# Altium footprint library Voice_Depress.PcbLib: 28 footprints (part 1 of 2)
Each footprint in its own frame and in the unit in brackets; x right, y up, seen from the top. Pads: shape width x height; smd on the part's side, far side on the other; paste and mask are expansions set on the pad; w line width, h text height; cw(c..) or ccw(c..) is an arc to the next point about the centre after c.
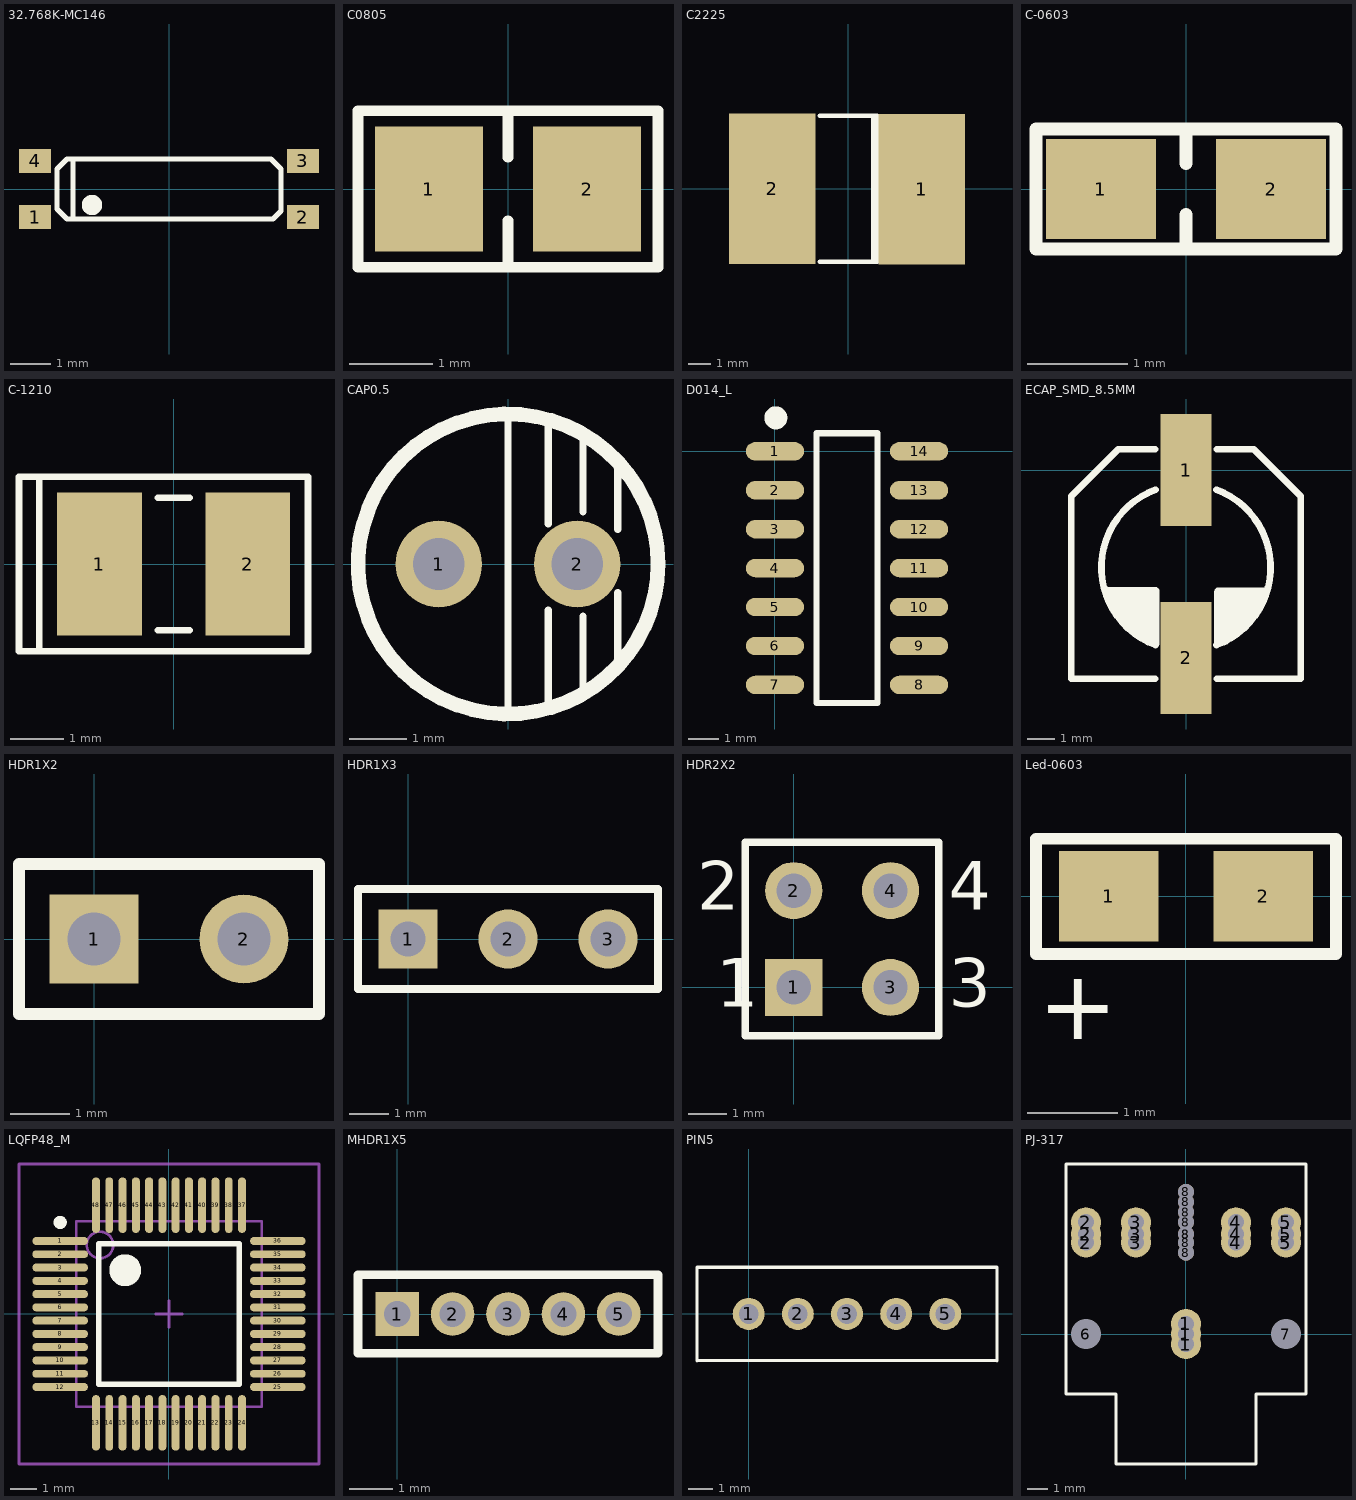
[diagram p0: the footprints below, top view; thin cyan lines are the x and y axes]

## 32.768K-MC146 [mm] "XTAL-32.768K"
pads (4):
  rect 0.8x0.6 smd: 1(-3.35,-0.7) 2(3.35,-0.7) 3(3.35,0.7) 4(-3.35,0.7)
Top Overlay:
  circle w0.254: c-1.927,-0.4 r0.127
  lines w0.127: -2.4,-0.75 -2.4,0.75 ; -2.8,-0.5 -2.55,-0.75 2.6,-0.75 2.8,-0.55 2.8,0.5 2.55,0.75 -2.55,0.75 -2.8,0.5 -2.8,-0.5

## C0805 [mm]
pads (2):
  rect 1.3x1.5 smd: 1(-0.95,0) 2(0.95,0)
Top Overlay:
  lines w0.127: 0,-0.94 0,-0.381 ; 0,0.381 0,0.889 ; -1.803,-0.94 -1.803,0.94 1.803,0.94 1.803,-0.94 -1.803,-0.94
3D body: height 1.2, standoff 0, extent -1.016,-0.584 0.984,0.616

## C2225 [mm] "Chip Capacitor; Body 5.6 x 6.4 mm (LxW typ)"
height 1.1
pads (2):
  rect 3.9x6.8 smd: 1(3.302,-0.025) 2(-3.429,0)
Top Overlay:
  lines w0.2: -1.3,-3.3 1.3,-3.3 1.3,3.3 -1.3,3.3 ; 1.11,-3.3 1.11,3.3
3D body: height 4.5, standoff -0.01, extent -2.857,-2.6 2.857,2.6

## C-0603 [mm]
height 0.5
pads (2):
  rect 1.1x1 smd: 1(-0.85,0) 2(0.85,0)
Top Overlay:
  lines w0.127: 0,-0.6 0,-0.254 ; 0,0.254 0,0.6 ; -1.5,-0.6 1.5,-0.6 1.5,0.6 -1.5,0.6 -1.5,-0.6
3D body: height 0.6, standoff 0, extent -0.813,-0.406 0.787,0.394

## C-1210 [mm]
height 4
pads (2):
  rect 1.6x2.7 smd: 1(-1.4,0) 2(1.4,0)
Top Overlay:
  lines w0.127: -0.3,-1.25 0.3,-1.25 ; -0.3,1.25 0.3,1.25 ; -2.54,-1.651 -2.921,-1.651 -2.921,1.651 -2.54,1.651 ; -2.54,-1.651 2.54,-1.651 2.54,1.651 -2.54,1.651 ; -2.54,-1.651 -2.54,1.651
3D body: height 1.9, standoff 0, extent -1.753,-1.397 1.747,1.403

## CAP0.5 [mm] "47uF"
pads (2):
  round 1.5 hole 0.9: 1(-1.2,0) 2(1.2,0)
Top Overlay:
  circle w0.254: c0,0 r2.6
  lines w0.127: 0,-2.6 0,2.6 ; 0.7,-2.5 0.7,-0.8 ; 0.7,0.7 0.7,2.5 ; 1.3,-2.3 1.3,-0.9 ; 1.3,0.9 1.3,2.2 ; 1.9,-1.7 1.9,-0.5 ; 1.9,0.6 1.9,1.7
3D body: height 13.03, standoff -3.01, extent -3.181,-3.099 3.17,3.252

## D014_L [mm]
pads (14):
  oval 1.9x0.6 smd: 1(0,0) 2(0,-1.27) 3(0,-2.54) 4(0,-3.81) 5(0,-5.08) 6(0,-6.35) 7(0,-7.62) 8(4.7,-7.62) 9(4.7,-6.35) 10(4.7,-5.08) 11(4.7,-3.81) 12(4.7,-2.54) 13(4.7,-1.27) 14(4.7,0)
Top Overlay:
  circle w0.5: c0.027,1.092 r0.125
  lines w0.2: 1.35,-8.21 3.35,-8.21 3.35,0.59 1.35,0.59 1.35,-8.21
3D body: height 1.55, standoff -0.05, extent -0.66,-8.155 5.33,0.535

## ECAP_SMD_8.5MM [mm] "铝电解电容"
height 13
pads (2):
  rect 1.9x4.15 smd: 1(0,0) 2(0,-6.95)
Top Overlay:
  lines w0.25: -2.877,-4.725 -1.127,-4.725 ; -2.627,-5.225 -1.127,-5.225 ; -2.127,-5.725 -1.127,-5.725 ; -1.143,-7.725 -4.25,-7.725 -4.25,-0.975 -2.5,0.775 -1.143,0.775 ; -1.127,-6.475 cw(c-0.064,-3.6) -1.127,-0.725 ; 1.127,-6.475 ccw(c0.064,-3.6) 1.127,-0.725 ; 1.143,-7.725 4.25,-7.725 4.25,-0.975 2.5,0.775 1.143,0.775 ; 1.177,-4.475 2.927,-4.475
  lines w0.3: -2.877,-4.475 -1.127,-4.475 -1.127,-6.425 ; -2.627,-4.975 -1.127,-4.975 ; -2.377,-5.475 -1.127,-5.475 ; -1.627,-5.975 -1.127,-5.975 ; -1.377,-6.225 -1.127,-6.225 ; 1.177,-6.375 1.177,-4.525
  lines w0.4: -2.727,-4.825 -1.377,-6.175 ; 1.427,-6.275 1.427,-4.575 ; 1.727,-6.075 1.727,-4.575 ; 2.027,-5.775 2.027,-4.625 ; 2.277,-5.475 2.277,-4.575 ; 2.527,-5.175 2.527,-4.575 ; 2.677,-4.825 2.677,-4.575
3D body: height 7.7, standoff 0, extent -3.298,-7.31 3.302,-0.31

## HDR1X2 [mm] "Connector; Header; 2 Position"
pads (2):
  rect 1.5x1.5 hole 0.9: 1(0,0)
  round 1.5 hole 0.9: 2(2.54,0)
Top Overlay:
  lines w0.2: -1.27,-1.27 3.81,-1.27 3.81,1.27 -1.27,1.27 -1.27,-1.27
3D body: height 7.58, standoff -2.94, extent -1.27,-1.27 1.27,1.27
3D body: height 7.58, standoff -2.94, extent 1.27,-1.27 3.81,1.27

## HDR1X3 [mm] "Connector; Header; 3 Position"
pads (3):
  rect 1.5x1.5 hole 0.9: 1(0,0)
  round 1.5 hole 0.9: 2(2.54,0) 3(5.08,0)
Top Overlay:
  lines w0.2: -1.27,-1.27 -1.27,1.27 6.35,1.27 6.35,-1.27 -1.27,-1.27
3D body: height 7.58, standoff -2.94, extent -1.27,-1.27 1.27,1.27
3D body: height 7.58, standoff -2.94, extent 1.27,-1.27 3.81,1.27
3D body: height 7.58, standoff -2.94, extent 3.81,-1.27 6.35,1.27

## HDR2X2 [mm] "Connector; Header; 2x2 Position"
pads (4):
  rect 1.5x1.5 hole 0.9: 1(0,0)
  round 1.5 hole 0.9: 2(0,2.54) 3(2.54,0) 4(2.54,2.54)
Top Overlay:
  lines w0.2: -1.27,-1.27 3.81,-1.27 3.81,3.81 -1.27,3.81 -1.27,-1.27
  text "1" at -2.032,-0.508 h1.27
  text "2" at -2.54,2.032 h1.27
  text "4" at 4.064,2.032 h1.27
  text "3" at 4.064,-0.508 h1.27
3D body: height 7.58, standoff -2.94, extent 1.27,1.27 3.81,3.81
3D body: height 7.58, standoff -2.94, extent -1.27,1.27 1.27,3.81
3D body: height 7.58, standoff -2.94, extent 1.27,-1.27 3.81,1.27
3D body: height 7.58, standoff -2.94, extent -1.27,-1.27 1.27,1.27

## Led-0603 [mm]
pads (2):
  rect 1.1x1 smd: 1(-0.85,0) 2(0.85,0)
Top Overlay:
  lines w0.127: -1.651,-0.635 1.651,-0.635 1.651,0.635 -1.651,0.635 -1.651,-0.635
  text "+" at -1.626,-1.575 h0.76
3D body: height 0.85, standoff 0.01, extent -1.021,-0.453 1.041,0.453

## LQFP48_M [mm] "Thin QFP, 48-Leads, Body 7x7mm, Pitch 0.5mm, IPC Low Density"
height 1.6
pads (48):
  oval 2.1x0.3 smd: 1(-4.1,2.75) 2(-4.1,2.25) 3(-4.1,1.75) 4(-4.1,1.25) 5(-4.1,0.75) 6(-4.1,0.25) 7(-4.1,-0.25) 8(-4.1,-0.75) 9(-4.1,-1.25) 10(-4.1,-1.75) 11(-4.1,-2.25) 12(-4.1,-2.75) 25(4.1,-2.75) 26(4.1,-2.25) 27(4.1,-1.75) 28(4.1,-1.25) 29(4.1,-0.75) 30(4.1,-0.25) 31(4.1,0.25) 32(4.1,0.75) 33(4.1,1.25) 34(4.1,1.75) 35(4.1,2.25) 36(4.1,2.75)
  oval 0.3x2.1 smd: 13(-2.75,-4.1) 14(-2.25,-4.1) 15(-1.75,-4.1) 16(-1.25,-4.1) 17(-0.75,-4.1) 18(-0.25,-4.1) 19(0.25,-4.1) 20(0.75,-4.1) 21(1.25,-4.1) 22(1.75,-4.1) 23(2.25,-4.1) 24(2.75,-4.1) 37(2.75,4.1) 38(2.25,4.1) 39(1.75,4.1) 40(1.25,4.1) 41(0.75,4.1) 42(0.25,4.1) 43(-0.25,4.1) 44(-0.75,4.1) 45(-1.25,4.1) 46(-1.75,4.1) 47(-2.25,4.1) 48(-2.75,4.1)
Top Overlay:
  circle w0.25: c-4.1,3.45 r0.125
  circle w0.6: c-1.65,1.65 r0.3
  lines w0.2: -2.65,-2.65 -2.65,2.65 2.65,2.65 2.65,-2.65 -2.65,-2.65
Mechanical 13:
  circle w0.1: c-2.6,2.6 r0.5
  lines w0.1: -3.5,-3.5 -3.5,3.5 3.5,3.5 3.5,-3.5 -3.5,-3.5
Mechanical 15:
  lines w0.1: -0.5,0 0.5,0 ; 0,-0.5 0,0.5 ; -5.65,-5.65 -5.65,5.65 5.65,5.65 5.65,-5.65 -5.65,-5.65
3D body: height 1.2, standoff 0, extent -4.475,-4.496 4.525,4.504

## MHDR1X5 [mm] "Connector; Header; 5 Position"
pads (5):
  rect 1x1 hole 0.6: 1(0,0)
  round 1 hole 0.6: 2(1.27,0) 3(2.54,0) 4(3.81,0) 5(5.08,0)
Top Overlay:
  lines w0.2: -0.9,-0.9 -0.9,0.9 5.98,0.9 5.98,-0.9 -0.9,-0.9

## PIN5 [mm] "Connector; Plug"
height 4.3
pads (5):
  round 1.3 hole 0.8: 1(0,0) 2(2,0) 3(4,0) 4(6,0) 5(8,0)
Top Overlay:
  lines w0.127: -2.1,-1.905 -2.1,1.9 10.1,1.9 ; -2.1,-1.9 10.1,-1.9 ; 10.1,-1.905 10.1,1.85

## PJ-317 [mm] "音频座"
height 10
pads (25):
  round 1.5 hole 0.8: 1(0,-0.508) 1(0,0) 1(0,0.508) 2(-5,4.572) 2(-5,5) 2(-5,5.588) 3(-2.5,4.572) 3(-2.5,5) 3(-2.5,5.588) 4(2.5,4.572) 4(2.5,5) 4(2.5,5.588) 5(5,4.572) 5(5,5) 5(5,5.588)
  round 1 hole 1.5: 6(-5,0) 7(5,0)
  round 0.8 hole 0.8: 8(0,4.064) 8(0,4.572) 8(0,5) 8(0,5) 8(0,5.588) 8(0,6.096) 8(0,6.604) 8(0,7.112)
Top Overlay:
  lines w0.127: -6,-3 -6,8.5 6,8.5 6,-3 3.5,-3 3.5,-6.5 -3.5,-6.5 -3.5,-3 -6,-3
3D body: height 3.2, standoff -10.8, extent -6.05,-6.553 6.05,8.547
